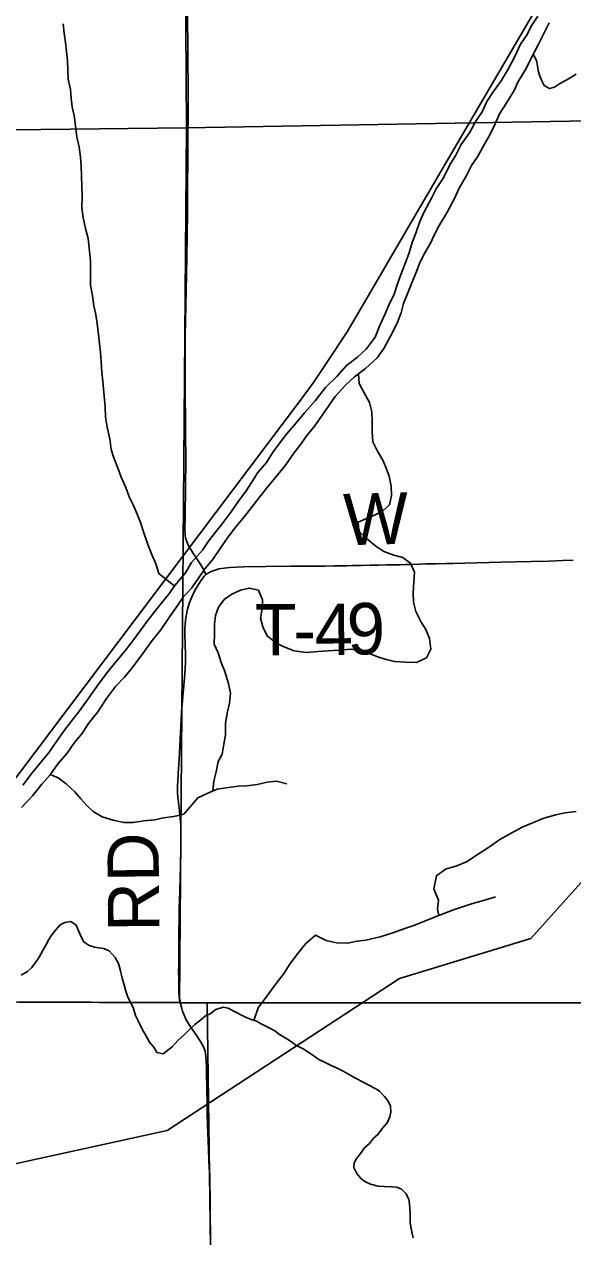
# Model space of a CAD drawing. Extents: x 1985906 to 2360102, y 891258 to 1222054.
# Drawn here: x 2113680 to 2116886, y 992198 to 999280 of the extents above; entities that cross this region are included whole.
import ezdxf

# ---------------------------------------------------------------- set-up
doc = ezdxf.new("R2010")
doc.units = 0
for name, color, linetype in [('GM_X_Major_River', 7, 'Continuous'), ('GM_X_Minor_River', 7, 'Continuous'), ('GM_X_Rail_Line', 7, 'Continuous'), ('GM_X_Section', 7, 'Continuous'), ('GM_X_Township', 7, 'Continuous'), ('GM_X_Township_Road', 7, 'Continuous'), ('GM_X_Township_Road_Text', 7, 'Continuous')]:
    doc.layers.add(name, color=color, linetype=linetype)

msp = doc.modelspace()

# ---------------------------------------------------------------- linework, layer by layer
at = {"layer": 'GM_X_Major_River'}
for points in [[(2116682.6, 999327.3), (2116646.9, 999275), (2116615.2, 999214.8), (2116581.5, 999162.5), (2116547.9, 999092.2), (2116508.3, 999017.9), (2116468.7, 998949.5), (2116417.1, 998879.2), (2116383.4, 998828.9), (2116357.7, 998768.7), (2116320, 998714.4), (2116282.4, 998646.1), (2116234.8, 998577.7), (2116203.1, 998515.4), (2116167.4, 998459.2), (2116129.8, 998382.8), (2116088.2, 998318.5), (2116060.5, 998264.3), (2116016.9, 998183.9), (2115993.2, 998127.7), (2115969.6, 998059.4), (2115947.9, 998005.2), (2115930.2, 997945), (2115906.5, 997882.8), (2115878.9, 997812.5), (2115859.2, 997758.3), (2115841.5, 997704.1), (2115811.8, 997639.8), (2115790.1, 997587.6), (2115756.5, 997517.3), (2115730.8, 997453.1), (2115679.2, 997382.7), (2115627.5, 997334.4), (2115563.8, 997286), (2115506.2, 997221.6), (2115440.6, 997159.1), (2115381.1, 997080.7), (2115319.5, 997012.3), (2115269.8, 996951.9), (2115212.2, 996885.5), (2115168.5, 996827.2), (2115130.8, 996776.9), (2115095.2, 996720.6), (2115045.5, 996662.3), (2115011.8, 996610), (2114974.1, 996549.7), (2114936.4, 996499.4), (2114888.8, 996431.1), (2114837.2, 996362.7), (2114797.5, 996312.4), (2114757.8, 996260.1), (2114722.1, 996207.8), (2114658.5, 996135.4), (2114622.9, 996075.1), (2114559.3, 996002.7), (2114523.6, 995948.4)], [(2114571.9, 995878.5), (2114609.6, 995932.8), (2114657.2, 995987.1), (2114694.9, 996039.4), (2114734.6, 996099.7), (2114780.3, 996152), (2114825.9, 996218.3), (2114871.5, 996286.7), (2114919.2, 996347), (2114966.8, 996405.4), (2115008.5, 996457.7), (2115054.2, 996518), (2115107.8, 996584.4), (2115163.4, 996652.8), (2115207.1, 996705.1), (2115256.7, 996775.5), (2115296.4, 996827.8), (2115332.1, 996878.1), (2115377.8, 996934.4), (2115427.4, 997004.8), (2115463.1, 997055), (2115496.8, 997105.3), (2115558.4, 997171.7), (2115610.1, 997220), (2115673.8, 997268.4), (2115743.4, 997330.9), (2115781.1, 997385.2), (2115820.7, 997457.5), (2115858.3, 997529.8), (2115883.9, 997594.1), (2115897.7, 997648.3), (2115917.4, 997700.5), (2115941.1, 997760.7), (2115972.7, 997835), (2115994.4, 997891.2), (2116020.1, 997941.4), (2116053.8, 998001.7), (2116077.5, 998051.9), (2116105.2, 998104.2), (2116150.8, 998178.5), (2116192.4, 998258.9), (2116222, 998323.1), (2116265.6, 998395.5), (2116295.3, 998453.8), (2116329, 998506), (2116362.7, 998566.3), (2116394.4, 998620.5), (2116426, 998684.8), (2116457.6, 998757.1), (2116501.3, 998823.4), (2116542.9, 998891.8), (2116564.6, 998942), (2116614.2, 999020.4), (2116641.8, 999078.6), (2116681.4, 999155), (2116721, 999233.3), (2116748.7, 999287.5)], [(2114523.6, 995948.4), (2114462, 995875.9), (2114400.5, 995795.5), (2114356.8, 995737.2), (2114315.2, 995678.9), (2114267.5, 995618.5), (2114207.9, 995546.1), (2114166.2, 995495.8), (2114124.6, 995439.5), (2114080.9, 995379.2), (2114043.2, 995326.9), (2114003.5, 995270.6), (2113953.9, 995208.2), (2113910.2, 995149.9), (2113868.6, 995091.6), (2113824.9, 995029.2), (2113771.3, 994962.9), (2113725.6, 994908.5), (2113672, 994836.1)], [(2113664.7, 994705.9), (2113728.3, 994774.3), (2113781.9, 994840.7), (2113829.6, 994895), (2113877.2, 994961.4), (2113930.8, 995021.7), (2113974.4, 995084.1), (2114016.1, 995136.4), (2114055.8, 995196.7), (2114109.4, 995263.1), (2114161, 995341.5), (2114212.6, 995411.8), (2114266.2, 995466.2), (2114315.9, 995528.6), (2114373.4, 995605), (2114427, 995681.4), (2114478.6, 995743.8), (2114526.2, 995814.1), (2114571.9, 995878.5)]]:
    msp.add_lwpolyline(points, dxfattribs=at)
at = {"layer": 'GM_X_Minor_River'}
for points in [[(2122569.5, 1002172.8), (2122567.2, 1000136.7), (2120927.7, 998804.4), (2119205.5, 996792.2), (2116640.5, 993940.5), (2115872.6, 993706.4), (2114514.6, 992818.2), (2111818.8, 992228.9)], [(2114557.8, 996000.4), (2114509.7, 996037), (2114465.9, 996071.2), (2114448.2, 996127.4), (2114424.4, 996187.6), (2114400.7, 996247.9), (2114379, 996310.1), (2114359.3, 996370.3), (2114339.5, 996418.4), (2114317.7, 996468.6), (2114293.9, 996518.8), (2114274.2, 996575), (2114246.5, 996635.3), (2114224.7, 996693.5), (2114203, 996747.7), (2114187.2, 996795.8), (2114179.4, 996858), (2114163.7, 996926.2), (2114154, 996984.3), (2114152.2, 997044.4), (2114144.5, 997128.6), (2114138.8, 997194.8), (2114133, 997246.9), (2114129.3, 997309), (2114125.5, 997363.1), (2114119.7, 997413.2), (2114113.9, 997469.4), (2114106.1, 997529.5), (2114098.4, 997583.6), (2114086.6, 997635.8), (2114078.8, 997693.9), (2114067.1, 997756.1), (2114067.4, 997846.2), (2114067.6, 997896.3), (2114061.8, 997954.4), (2114054.1, 998028.6), (2114038.4, 998086.8), (2114024.7, 998151), (2114016.9, 998205.1), (2114019.2, 998277.2), (2114017.4, 998335.3), (2114013.6, 998393.4), (2114011.8, 998451.5), (2114008, 998503.6), (2114000.3, 998561.8), (2113986.5, 998621.9), (2113978.8, 998686.1), (2113971, 998746.2), (2113959.2, 998796.4), (2113953.4, 998846.5), (2113949.7, 998898.6), (2113935.9, 998958.8), (2113934.1, 999010.9), (2113932.3, 999067), (2113926.5, 999121.1), (2113920.8, 999173.2), (2113913, 999227.3), (2113907.2, 999281.5)], [(2116655.2, 999104.4), (2116673.4, 999068.2), (2116679.4, 999036.1), (2116683.5, 999010), (2116691.5, 998981.9), (2116705.5, 998949.8), (2116719.6, 998921.7), (2116749.6, 998903.6), (2116779.6, 998911.5), (2116809.5, 998931.5), (2116843.5, 998951.6), (2116875.4, 998969.6), (2116905.4, 998987.6)], [(2115633, 997237.4), (2115638.2, 997181.4), (2115667.9, 997127.2), (2115697.6, 997071), (2115711.4, 997016.8), (2115713.2, 996956.7), (2115712.9, 996898.6), (2115716.7, 996840.5), (2115744.5, 996786.3), (2115776.2, 996734), (2115796, 996687.8), (2115813.8, 996639.7), (2115825.5, 996581.5), (2115827.3, 996527.4), (2115815.1, 996473.4), (2115775.1, 996437.5), (2115731.1, 996413.7), (2115681.1, 996393.9), (2115631.1, 996372.1), (2115634.9, 996320), (2115680.6, 996275.7), (2115734.4, 996231.3), (2115782.2, 996201.1), (2115840, 996178.8), (2115893.8, 996164.5), (2115937.6, 996132.2), (2115961.4, 996080), (2115957.2, 996021.9), (2115952.9, 995961.8), (2115954.7, 995903.7), (2115968.5, 995849.6), (2116000.2, 995787.3), (2116028, 995745.1), (2116049.8, 995692.9), (2116057.5, 995630.8), (2116031.3, 995578.8), (2115973.3, 995553), (2115909.5, 995553.3), (2115845.6, 995557.7), (2115795.7, 995569.9), (2115745.9, 995584.2), (2115696, 995604.5), (2115642.2, 995622.8), (2115592.3, 995629), (2115518.4, 995623.4), (2115456.5, 995619.7), (2115398.6, 995615.9), (2115326.7, 995610.3), (2115256.8, 995620.6), (2115193, 995645), (2115149.2, 995669.2), (2115099.4, 995707.5), (2115073.7, 995759.8), (2115061.9, 995811.9), (2115070.1, 995866), (2115072.3, 995918), (2115048.6, 995974.2), (2114994.7, 995986.5), (2114944.7, 995974.8), (2114892.7, 995951), (2114848.7, 995919.1), (2114814.6, 995875.2), (2114798.4, 995827.2), (2114792.2, 995775.2), (2114792, 995715), (2114789.8, 995659), (2114813.6, 995608.8), (2114831.3, 995552.6), (2114853.1, 995500.4), (2114874.8, 995430.2), (2114886.5, 995372), (2114880.3, 995313.9), (2114866.1, 995255.9), (2114855.9, 995195.8), (2114855.7, 995129.7), (2114847.5, 995075.7), (2114837.3, 995017.6), (2114813.1, 994973.7), (2114800.9, 994913.6), (2114788.7, 994859.6), (2114782.5, 994803.5)], [(2113831.3, 994897.5), (2113878.4, 994878), (2113924.2, 994843.8), (2113975.9, 994797.4), (2114009.7, 994755.2), (2114045.5, 994717), (2114083.3, 994682.7), (2114135.1, 994650.4), (2114198.9, 994632.1), (2114262.7, 994617.7), (2114318.6, 994617.5), (2114378.6, 994627.2), (2114442.5, 994632.9), (2114494.4, 994644.7), (2114554.4, 994652.4), (2114612.3, 994666.1), (2114650.4, 994710), (2114694.5, 994761.9), (2114752.5, 994789.7), (2114808.5, 994811.4), (2114860.5, 994819.2), (2114930.4, 994828.9), (2114980.3, 994832.6), (2115042.2, 994840.3), (2115100.2, 994854.1), (2115154.1, 994859.8), (2115213.9, 994843.5)], [(2116103.4, 994074.8), (2116096.4, 994112.2), (2116102.1, 994164.4), (2116073.8, 994230.4), (2116089.4, 994306.6), (2116143.2, 994344.9), (2116209, 994365.3), (2116264.8, 994387.6), (2116332.5, 994432), (2116394.2, 994472.4), (2116459.9, 994518.8), (2116525.7, 994555.1), (2116591.4, 994589.5), (2116657.2, 994617.9), (2116717, 994642.2), (2116786.8, 994662.6), (2116840.7, 994674.9), (2116906.6, 994681.2)], [(2115022.3, 993461.5), (2115046.5, 993536.1), (2115088.2, 993590.4), (2115145.7, 993668.8), (2115199.3, 993737.2), (2115231, 993787.5), (2115278.7, 993851.8), (2115324.3, 993908.2), (2115382, 993960.5), (2115444.1, 993928.8), (2115506.1, 993915), (2115572, 993913.3), (2115623.9, 993923.6), (2115675.8, 993929.9), (2115759.6, 993950.3), (2115835.4, 993972.7), (2115905.1, 993999.1), (2115957, 994015.4), (2116038.7, 994049.8), (2116112.5, 994078.2), (2116188.3, 994106.7), (2116242.1, 994124.9), (2116294, 994143.2), (2116363.8, 994161.6), (2116435.6, 994184)], [(2113662.2, 993725.6), (2113698.2, 993747.6), (2113724.1, 993771.7), (2113746.1, 993799.7), (2113768, 993831.8), (2113790, 993873.9), (2113805.9, 993902), (2113823.9, 993934), (2113841.8, 993962.1), (2113863.8, 993990.2), (2113889.7, 994020.2), (2113917.7, 994034.2), (2113951.7, 994040.2), (2113983.7, 994018.1), (2113999.7, 993981.9), (2114013.8, 993945.8), (2114027.8, 993919.7), (2114055.8, 993901.6), (2114089.8, 993889.5), (2114115.8, 993885.4), (2114145.8, 993881.4), (2114175.8, 993867.3), (2114211.9, 993829.1), (2114229.9, 993794.9), (2114242, 993750.8), (2114252, 993708.6), (2114266.1, 993662.4), (2114274.2, 993632.3), (2114286.2, 993598.2), (2114304.3, 993560.1), (2114318.3, 993531.9), (2114330.3, 993489.8), (2114346.4, 993459.7), (2114370.4, 993407.4), (2114388.5, 993377.3), (2114412.5, 993335.2), (2114436.6, 993305), (2114454.6, 993274.9), (2114492.6, 993266.8), (2114544.5, 993306.8), (2114580.5, 993346.9), (2114612.4, 993375), (2114642.4, 993405), (2114676.3, 993437.1), (2114712.2, 993465.1), (2114740.2, 993489.1), (2114766.2, 993501.1), (2114800.1, 993525.2), (2114842.1, 993539.1), (2114872.1, 993533.1), (2114902.1, 993517), (2114970.1, 993482.7), (2115006.1, 993466.6), (2115038.1, 993456.5), (2115064.2, 993442.5), (2115116.2, 993416.3)], [(2115116.2, 993416.3), (2115144.2, 993400.2), (2115172.2, 993380.1), (2115214.2, 993353.9), (2115242.2, 993335.8), (2115268.3, 993317.7), (2115310.3, 993295.6), (2115338.3, 993277.5), (2115374.3, 993253.3), (2115402.3, 993233.2), (2115438.3, 993215.1), (2115470.4, 993201), (2115508.4, 993182.9), (2115544.4, 993164.8), (2115584.4, 993142.7), (2115616.4, 993124.5), (2115660.4, 993100.4), (2115694.5, 993084.3), (2115730.5, 993064.2), (2115756.5, 993048.1), (2115786.5, 993017.9), (2115806.6, 992989.8), (2115820.6, 992961.7), (2115822.6, 992925.6), (2115816.7, 992899.5), (2115800.7, 992863.4), (2115774.8, 992833.3), (2115746.9, 992795.3), (2115720.9, 992773.2), (2115699, 992743.2), (2115669, 992717.1), (2115645.1, 992685.1), (2115623.1, 992657), (2115609.1, 992630.9), (2115607.2, 992602.9), (2115623.2, 992566.7), (2115649.3, 992536.6), (2115675.3, 992518.5), (2115703.3, 992504.4), (2115749.3, 992494.3), (2115783.3, 992492.2), (2115827.3, 992490.2), (2115857.3, 992488.1), (2115885.3, 992476), (2115911.3, 992449.9), (2115927.3, 992417.8), (2115931.4, 992387.7), (2115935.5, 992337.5), (2115935.5, 992281.3), (2115939.6, 992255.2), (2115947.6, 992217.1), (2115953.7, 992191)]]:
    msp.add_lwpolyline(points, dxfattribs=at)
at = {"layer": 'GM_X_Rail_Line'}
msp.add_lwpolyline([(2107918.1, 987312.2), (2109027.9, 988781.7), (2115283.8, 997068.6), (2115370.8, 997187.7), (2115464.4, 997326.6), (2115566.7, 997483.2), (2115705.7, 997719.2), (2115857.7, 997978.8), (2116209.4, 998579), (2117111.6, 1000121.6), (2117725.7, 1001170), (2117921.6, 1001517.2), (2118014.1, 1001702.3), (2118112.4, 1001931.1), (2118994.8, 1004188.6), (2119493.5, 1005469.5), (2119807.1, 1006232.8), (2120298.3, 1007490.8), (2121825.6, 1011363.7)], dxfattribs=at)
at = {"layer": 'GM_X_Section'}
for points in [[(2114593.4, 1004032.5), (2119854.2, 1004093.4), (2119853.9, 1002528.5), (2119928.2, 998880.6), (2117651.8, 998728.2), (2114628.3, 998675.3)], [(2108514.3, 1003954.6), (2114593.4, 1004032.5), (2114628.3, 998675.3), (2108501.2, 998604.9), (2108511.1, 998947.2)], [(2119928.2, 998880.6), (2119903.4, 993563.5), (2114748.4, 993565.3), (2114588.3, 993564.3), (2114628.3, 998675.3), (2117651.8, 998728.2)], [(2114628.3, 998675.3), (2114588.3, 993564.3), (2108468.6, 993590), (2108501.2, 998604.9)], [(2114748.4, 993565.3), (2114821.5, 988281), (2108487.7, 988311.4), (2108468.6, 993590), (2114588.3, 993564.3)], [(2114748.4, 993565.3), (2119903.4, 993563.5), (2120049.5, 993560.5), (2120191.2, 988188.5), (2114821.5, 988281)]]:
    msp.add_lwpolyline(points, close=True, dxfattribs=at)
at = {"layer": 'GM_X_Township'}
for points in [[(2133580.3, 1009513.3), (2133246.9, 1009511.7), (2131763.4, 1009478), (2130671.8, 1009465.5), (2130250.8, 1009485.4), (2128830.9, 1009460.8), (2128435, 1009462.4), (2126795.7, 1009468.8), (2125157.2, 1009475.3), (2125184.4, 1004143.8), (2122462.2, 1004110.5), (2119835.2, 1004078.3), (2119909.8, 996227.8), (2119898.4, 993557.9), (2114579.5, 993566.9), (2108482.3, 993590), (2108479.9, 994295.6), (2108521.6, 1004617.7), (2108488.7, 1009238.5), (2108481.1, 1010602)], [(2108482.3, 993590), (2114579.5, 993566.9), (2119898.4, 993557.9), (2119909.8, 996227.8), (2119835.2, 1004078.3), (2122462.2, 1004110.5), (2125184.4, 1004143.8), (2125157.2, 1009475.3), (2126795.7, 1009468.8), (2128435, 1009462.4), (2128830.9, 1009460.8), (2130250.8, 1009485.4), (2130671.8, 1009465.5), (2131763.4, 1009478), (2133246.9, 1009511.7), (2133580.3, 1009513.3)]]:
    msp.add_lwpolyline(points, dxfattribs=at)
at = {"layer": 'GM_X_Township_Road'}
for points in [[(2114620.8, 997434), (2114621.5, 997460), (2114626.1, 997722.3), (2114630.4, 997919.1), (2114632.5, 998050.2), (2114633.5, 998181.3), (2114634.6, 998312.5), (2114635.3, 998509.3), (2114637.4, 998870.2), (2114636.5, 999116.2), (2114634.3, 999345.8), (2114632.6, 999493.4), (2114632.3, 999723), (2114631.6, 999919.9), (2114629.9, 1000133.1), (2114626.6, 1000461.1), (2114627.4, 1000707.2), (2114624.4, 1000887.5), (2114622, 1001166.3), (2114619.9, 1001313.8), (2114619.7, 1001378.6)], [(2114665.5, 996193.1), (2114657.5, 996205.5), (2114640.7, 996233.6), (2114633.6, 996248.4), (2114627.5, 996263.6), (2114622.9, 996279.3), (2114620.3, 996295.5), (2114619.3, 996328.3), (2114619.7, 996410.3), (2114624, 996738.3), (2114622.9, 996885.9), (2114620.6, 997197.6), (2114620.6, 997427.3), (2114620.8, 997434)], [(2114741.8, 996066.6), (2114727, 996094.4), (2114711.2, 996122.8), (2114665.5, 996193.1)], [(2114741.8, 996066.6), (2114755.2, 996074.5), (2114768.4, 996081.4), (2114784.2, 996088.4), (2114800.9, 996094.2), (2114816.8, 996098.3), (2114848.9, 996103.8), (2114881, 996106.7), (2114961.7, 996110.6), (2115092.8, 996113.2), (2115239, 996114.2), (2115294, 996114.5), (2115364.3, 996115), (2115436.4, 996115.5), (2115491, 996115.9), (2115533.9, 996116.2), (2115565, 996117.6), (2115597.8, 996118.2), (2115649.9, 996119.1), (2115701.2, 996120.1), (2115752.4, 996121), (2115798.4, 996121.8), (2115837.5, 996122.5), (2115877.9, 996123.2), (2115908.7, 996124.2), (2115936.4, 996125), (2115990.3, 996126.6), (2116027.7, 996127.8), (2116087.6, 996128.8), (2116145.8, 996129.8), (2116185.2, 996130.5), (2116326.3, 996134.2), (2116465.2, 996137.9), (2116550.4, 996140.2), (2116642.4, 996142), (2116745.7, 996144.1), (2116826.4, 996146.9), (2116888.1, 996149.1)], [(2114588.8, 993583.4), (2114586, 993596.6), (2114582.6, 993630.5), (2114582.6, 993671.2), (2114582.6, 993712), (2114582.5, 993743.3), (2114582.7, 993785.5), (2114582.7, 993917.1), (2114586.4, 994115.3), (2114588.8, 994217.3), (2114590.6, 994291.9), (2114594.7, 994442.8), (2114594.7, 994541.2), (2114594.7, 994602.2), (2114586.3, 994704), (2114577.8, 994765), (2114575.9, 994790.4), (2114575.7, 994812.5), (2114575.6, 994831.2), (2114576.8, 994856.5), (2114579.9, 994905.8), (2114584.6, 994983.8), (2114598.2, 995261.9), (2114618.9, 995485.9), (2114620.4, 995518.1), (2114622.1, 995551.9), (2114622.1, 995599.4), (2114620.5, 995655.4), (2114618.8, 995718.7), (2114619.2, 995751.6), (2114622.6, 995799.8), (2114627.7, 995832.4), (2114634.9, 995864.5), (2114644.3, 995896), (2114655.8, 995926.8), (2114669.4, 995956.7), (2114684.9, 995985.7), (2114702.5, 996013.4), (2114712.6, 996029), (2114722.5, 996043.1), (2114732.1, 996055.4), (2114741.8, 996066.6)], [(2114768, 992152.4), (2114765.9, 992383.5), (2114764.6, 992547.2), (2114764.1, 992563.7), (2114761.2, 992596.7), (2114754.1, 992758.6), (2114752.7, 992801.2), (2114751.3, 992850.7), (2114749.5, 992919), (2114749.2, 992958.3), (2114748.1, 993072.1), (2114746.1, 993145.9), (2114744.8, 993190.1), (2114741.4, 993251.8), (2114736.9, 993282.8), (2114728.4, 993306.6), (2114716.4, 993328.3), (2114687.9, 993372.5), (2114647.1, 993429.9), (2114625.3, 993469.7), (2114605.7, 993515.4), (2114601.3, 993531.2), (2114595.1, 993553.1), (2114588.8, 993583.4)]]:
    msp.add_lwpolyline(points, dxfattribs=at)

# ---------------------------------------------------------------- texts
at = {"layer": 'GM_X_Township_Road_Text'}
for s, rotation, p in [('W', 1.41529, (2115548.9, 996236.6)), ('T', 0.01714, (2115027.8, 995593.5)), ('4', 0.64658, (2115379, 995593.9)), ('9', 1.9576, (2115571.2, 995596.1)), ('-', 0.15937, (2115253, 995593.5)), ('RD', 90.48144, (2114469.8, 993980.8))]:
    msp.add_text(s, height=300, rotation=rotation, dxfattribs=at).set_placement(p)

doc.saveas('drawing.dxf')
